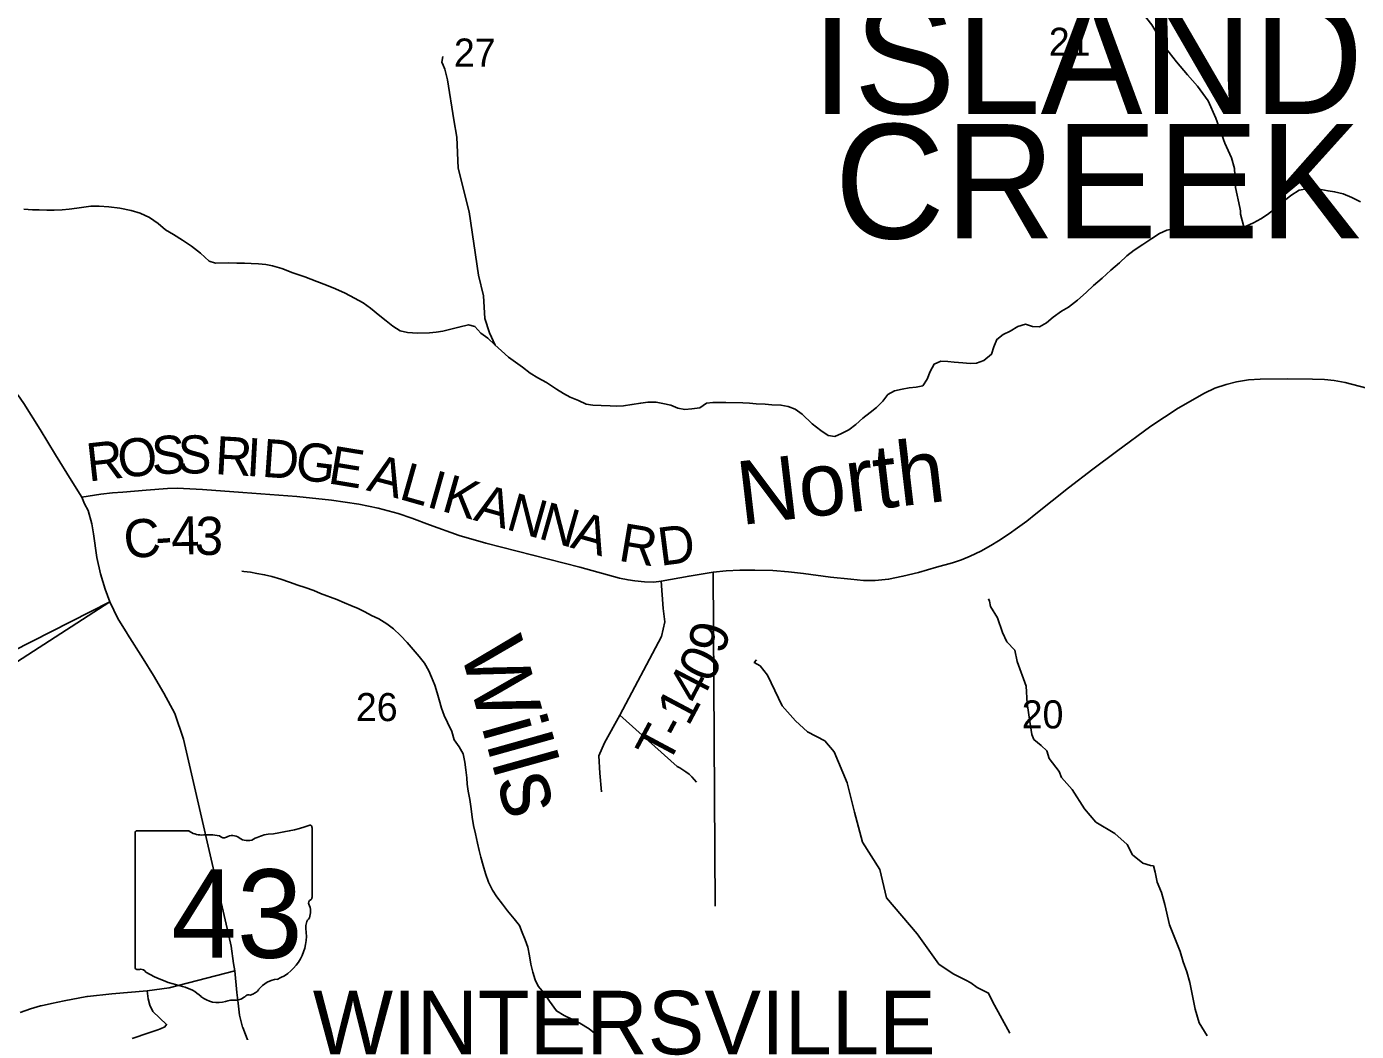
# Model space of a CAD drawing. Extents: x 0 to 34, y 0 to 22.
# Drawn here: x 5.55 to 7.533, y 16.768 to 18.266 of the extents above; entities that cross this region are included whole.
import ezdxf

# ---------------------------------------------------------------- set-up
doc = ezdxf.new("R2010")
doc.units = 0
for name, color, linetype in [('GM_X_Corporation_Text', 7, 'Continuous'), ('GM_X_County_Road', 7, 'Continuous'), ('GM_X_County_Road_Text', 7, 'Continuous'), ('GM_X_Minor_River', 7, 'Continuous'), ('GM_X_Minor_River_Text', 7, 'Continuous'), ('GM_X_Section_Text', 7, 'Continuous'), ('GM_X_State_Location', 7, 'Continuous'), ('GM_X_State_Route', 7, 'Continuous'), ('GM_X_State_Shield', 7, 'Continuous'), ('GM_X_Township_Road', 7, 'Continuous'), ('GM_X_Township_Road_Text', 7, 'Continuous'), ('GM_X_Township_Text', 7, 'Continuous'), ('SH_Data', 7, 'Continuous')]:
    doc.layers.add(name, color=color, linetype=linetype)

msp = doc.modelspace()

# ---------------------------------------------------------------- linework, layer by layer
at = {"layer": 'GM_X_County_Road'}
for points in [[(5.6321, 17.5648), (5.6607, 17.5691), (5.6781, 17.5712), (5.6934, 17.572), (5.7284, 17.5749), (5.7602, 17.5774), (5.7743, 17.5782), (5.8124, 17.5762), (5.8723, 17.5714), (5.9527, 17.5655), (6.0047, 17.5601), (6.0452, 17.554), (6.074, 17.5481), (6.1042, 17.5401), (6.1244, 17.5334), (6.1509, 17.5232), (6.1949, 17.5073), (6.2349, 17.4961), (6.305, 17.4782), (6.3752, 17.46), (6.4342, 17.444), (6.4468, 17.4412), (6.4571, 17.4398), (6.4713, 17.4384), (6.4851, 17.4379), (6.4965, 17.4392), (6.5378, 17.447), (6.5739, 17.453), (6.5934, 17.455), (6.6136, 17.4558), (6.636, 17.4559), (6.6628, 17.4553), (6.6863, 17.4534), (6.7087, 17.4508), (6.7487, 17.4455), (6.7791, 17.4421), (6.7978, 17.4405), (6.8152, 17.4402), (6.8353, 17.4423), (6.8568, 17.4468), (6.8802, 17.4525), (6.9071, 17.46), (6.9307, 17.4668), (6.9442, 17.4712), (6.9573, 17.4766), (6.973, 17.4843), (6.9879, 17.4927), (6.9992, 17.4997), (7.0151, 17.51), (7.0277, 17.5191), (7.0414, 17.529), (7.0548, 17.5399), (7.1036, 17.5784), (7.14, 17.6063), (7.1752, 17.6329), (7.2265, 17.6705), (7.2672, 17.6972), (7.3067, 17.7198), (7.3219, 17.727), (7.3387, 17.7328), (7.3544, 17.7367), (7.3722, 17.7393), (7.3898, 17.7406), (7.4303, 17.741), (7.4675, 17.7405), (7.4853, 17.7399), (7.5, 17.7385), (7.5164, 17.7354), (7.5485, 17.7269)], [(5.7439, 16.7699), (5.7495, 16.7717), (5.7561, 16.7747), (5.7586, 16.7785), (5.7382, 16.7979), (5.7337, 16.8072), (5.7311, 16.8168), (5.7296, 16.8288)], [(5.7074, 16.7573), (5.732, 16.7659), (5.7439, 16.7699)]]:
    msp.add_lwpolyline(points, dxfattribs=at)
at = {"layer": 'GM_X_Minor_River'}
for points in [[(7.3654, 17.9677), (7.3601, 17.9865), (7.3601, 17.9915), (7.3592, 17.9964), (7.353, 18.0263), (7.3514, 18.0545), (7.3469, 18.0707), (7.3367, 18.0926), (7.3232, 18.1296), (7.3122, 18.1553), (7.2959, 18.1771), (7.2812, 18.194), (7.2646, 18.2134), (7.2484, 18.2345), (7.2278, 18.2687), (7.2034, 18.2995), (7.1579, 18.3269), (7.1012, 18.348), (7.0317, 18.3655), (7.0137, 18.3807), (6.9548, 18.4193), (6.9266, 18.4318), (6.9232, 18.4344)], [(6.2486, 17.7914), (6.2402, 17.8094), (6.2333, 17.8309), (6.2312, 17.8647), (6.2239, 17.8954), (6.2097, 17.9902), (6.1935, 18.0549), (6.1915, 18.1013), (6.1873, 18.127), (6.1775, 18.1866), (6.1738, 18.2028), (6.1711, 18.2089), (6.1691, 18.213), (6.1705, 18.2218)], [(7.539, 18.0051), (7.5262, 18.0116), (7.5131, 18.0169), (7.5005, 18.0199), (7.4909, 18.0211), (7.4802, 18.0231), (7.4695, 18.0246), (7.4589, 18.0243), (7.4476, 18.0221), (7.4353, 18.0141), (7.4249, 18.0061), (7.4119, 17.9951), (7.4004, 17.986), (7.3907, 17.9796), (7.3795, 17.9735), (7.3686, 17.9686), (7.3566, 17.9652), (7.3464, 17.963), (7.3327, 17.9626), (7.3182, 17.9629), (7.3038, 17.9643), (7.2912, 17.9654), (7.2813, 17.9659), (7.2718, 17.9656), (7.2619, 17.9649), (7.2506, 17.9626), (7.2393, 17.9577), (7.2278, 17.9501), (7.2147, 17.9414)], [(6.1178, 17.8099), (6.1071, 17.8126), (6.0962, 17.8195), (6.0864, 17.8275), (6.0767, 17.8348), (6.0627, 17.8462), (6.0518, 17.8542), (6.039, 17.8614), (6.0251, 17.8686), (6.0108, 17.8754), (5.997, 17.8806), (5.9827, 17.8863), (5.965, 17.8929), (5.9469, 17.8992), (5.9308, 17.9055), (5.9166, 17.9097), (5.9066, 17.9116), (5.8956, 17.9124), (5.8849, 17.9128), (5.875, 17.9137), (5.8636, 17.9137), (5.8514, 17.9141), (5.8317, 17.9134), (5.8221, 17.9166), (5.8092, 17.9283), (5.7959, 17.9389), (5.7823, 17.9476), (5.7691, 17.956), (5.7571, 17.9632), (5.7462, 17.9724), (5.733, 17.9814), (5.7191, 17.9879), (5.7057, 17.992), (5.6892, 17.9953), (5.6728, 17.9974), (5.6579, 17.9985), (5.6458, 17.9985), (5.6246, 17.9955), (5.6136, 17.994), (5.603, 17.9929), (5.5908, 17.9926), (5.5802, 17.9926), (5.5688, 17.993), (5.5589, 17.9931), (5.5459, 17.9938)], [(7.2147, 17.9414), (7.2017, 17.933), (7.1906, 17.9243), (7.1799, 17.914), (7.1669, 17.903), (7.154, 17.8912), (7.141, 17.8801), (7.1303, 17.8699), (7.1173, 17.8584), (7.1036, 17.8481), (7.0935, 17.8417), (7.0809, 17.833), (7.0709, 17.8247), (7.0604, 17.8186), (7.0501, 17.8191), (7.0394, 17.8225), (7.0281, 17.8191), (7.0169, 17.8123), (7.0064, 17.807), (6.9968, 17.7999), (6.9922, 17.7887), (6.9887, 17.7776), (6.9776, 17.7681), (6.9667, 17.7644), (6.9572, 17.7641), (6.9461, 17.7648), (6.9332, 17.766), (6.9236, 17.7668), (6.9134, 17.7672), (6.9032, 17.7627), (6.8975, 17.7519), (6.8929, 17.7407), (6.8864, 17.7306), (6.8766, 17.7288), (6.8663, 17.7277), (6.8557, 17.7255), (6.844, 17.7229), (6.8343, 17.7176), (6.827, 17.7079), (6.8174, 17.6984), (6.8078, 17.6909), (6.797, 17.6826), (6.7867, 17.6731), (6.7763, 17.6652), (6.7654, 17.6595), (6.7553, 17.655), (6.7454, 17.6566), (6.7345, 17.6639), (6.7216, 17.6741), (6.7067, 17.6885), (6.6959, 17.6958), (6.6855, 17.6996), (6.6748, 17.7019), (6.6611, 17.7023), (6.6515, 17.7031), (6.6378, 17.7038), (6.6279, 17.7046), (6.618, 17.7051), (6.5929, 17.7058), (6.583, 17.7055), (6.5735, 17.7056), (6.564, 17.7049), (6.554, 17.6978), (6.5419, 17.6962), (6.5316, 17.6955), (6.5213, 17.6975), (6.5109, 17.7017), (6.4986, 17.7044), (6.4887, 17.706), (6.4765, 17.706), (6.4659, 17.7049), (6.4527, 17.7026), (6.4402, 17.7006), (6.4303, 17.7003), (6.4201, 17.7008), (6.4067, 17.7015), (6.3945, 17.7019), (6.3842, 17.7034), (6.373, 17.7088), (6.3607, 17.7137), (6.3507, 17.7191), (6.3402, 17.7256), (6.3251, 17.7354), (6.3123, 17.7426), (6.301, 17.7495), (6.2897, 17.7583), (6.2789, 17.7659), (6.2684, 17.7732), (6.2582, 17.7827), (6.248, 17.7919), (6.2378, 17.8015), (6.2273, 17.8092), (6.2186, 17.8188), (6.2087, 17.8215), (6.1947, 17.818), (6.1804, 17.8145), (6.1706, 17.8123), (6.1607, 17.8105), (6.1509, 17.8094), (6.133, 17.8089), (6.1178, 17.8099)], [(6.1688, 17.2499), (6.1654, 17.2623), (6.1624, 17.2729), (6.1586, 17.2845), (6.1537, 17.2962), (6.1496, 17.3059), (6.1435, 17.3172), (6.1356, 17.3272), (6.1265, 17.3375), (6.1175, 17.3479), (6.1076, 17.3582), (6.0971, 17.3682), (6.0869, 17.3758), (6.0753, 17.3831), (6.0645, 17.3884), (6.0541, 17.3938), (6.0444, 17.3988), (6.0336, 17.403), (6.024, 17.4069), (6.0128, 17.4119), (5.9882, 17.421), (5.9782, 17.4253), (5.9655, 17.4298), (5.9543, 17.4332), (5.942, 17.4378), (5.929, 17.4423), (5.9155, 17.4461), (5.9048, 17.4488), (5.8933, 17.4507), (5.8838, 17.4527), (5.8739, 17.4539), (5.8708, 17.4542)], [(7.3105, 16.7615), (7.2988, 16.7807), (7.2924, 16.8015), (7.2849, 16.8409), (7.28, 16.8571), (7.2745, 16.8719), (7.2701, 16.887), (7.2641, 16.9021), (7.2542, 16.927), (7.2473, 16.9573), (7.2424, 16.9751), (7.2357, 16.9906), (7.2332, 17.0057), (7.2304, 17.0148), (7.2262, 17.0155), (7.2144, 17.0191), (7.1991, 17.0314), (7.1912, 17.0468), (7.1728, 17.0633), (7.1445, 17.0803), (7.1275, 17.0998), (7.1093, 17.1287), (7.0931, 17.1467), (7.0899, 17.1558), (7.0748, 17.1749), (7.0716, 17.1866), (7.0631, 17.1945), (7.052, 17.2034), (7.0488, 17.2109), (7.0462, 17.2303), (7.0423, 17.2568), (7.0404, 17.283), (7.0272, 17.3197), (7.0235, 17.3367), (7.0116, 17.349), (7.0053, 17.363), (6.9977, 17.3849), (6.9876, 17.4015), (6.9859, 17.4094), (6.9844, 17.4128)], [(7.0163, 16.7654), (6.9905, 16.8128), (6.9846, 16.8253), (6.9675, 16.8337), (6.9579, 16.8404), (6.9506, 16.8445), (6.9445, 16.8474), (6.9319, 16.854), (6.9101, 16.8685), (6.878, 16.9136), (6.8324, 16.9672), (6.8222, 17.0095), (6.7965, 17.0502), (6.7848, 17.0952), (6.7734, 17.1387), (6.7544, 17.1848), (6.7401, 17.2012), (6.7146, 17.2149), (6.6965, 17.2313), (6.6768, 17.2534), (6.6549, 17.299), (6.644, 17.3129), (6.6352, 17.3181), (6.6382, 17.3219)], [(6.3993, 16.7636), (6.3891, 16.7721), (6.3748, 16.7803), (6.3628, 16.7864), (6.3516, 16.7918), (6.34, 16.7986), (6.3297, 16.8131), (6.3225, 16.8247), (6.313, 16.8354), (6.3085, 16.8452), (6.3047, 16.8565), (6.3021, 16.8682), (6.2998, 16.8806), (6.2975, 16.8935), (6.2933, 16.9048), (6.2892, 16.9157), (6.2851, 16.9262), (6.2768, 16.9358), (6.2673, 16.9477), (6.2594, 16.9577), (6.2514, 16.9688), (6.2446, 16.9789), (6.2386, 16.9905), (6.2344, 17.0033), (6.2306, 17.0153), (6.2275, 17.0278), (6.2249, 17.038), (6.2223, 17.0489), (6.2192, 17.0625), (6.2165, 17.075), (6.2146, 17.0875), (6.2131, 17.1), (6.2107, 17.1139), (6.2084, 17.1264), (6.207, 17.1366), (6.2063, 17.1461), (6.2052, 17.1579), (6.2037, 17.1696), (6.201, 17.1817), (6.195, 17.1925), (6.1874, 17.2026), (6.184, 17.215), (6.1775, 17.2285), (6.1726, 17.239), (6.1688, 17.2499)]]:
    msp.add_lwpolyline(points, dxfattribs=at)
at = {"layer": 'GM_X_State_Route'}
for points in [[(5.674, 17.4084), (5.6669, 17.4275), (5.6602, 17.4502), (5.6549, 17.4748), (5.6496, 17.5101), (5.6474, 17.5249), (5.6416, 17.5448), (5.6365, 17.5549), (5.6321, 17.5648), (5.6162, 17.5898), (5.5931, 17.6278), (5.5703, 17.6654), (5.5456, 17.704), (5.537, 17.7172)], [(5.6999, 17.3613), (5.6858, 17.3838), (5.674, 17.4084)], [(5.8605, 16.8585), (5.8585, 16.8695), (5.855, 16.8952), (5.849, 16.9213), (5.7839, 17.2037), (5.7709, 17.2423), (5.7544, 17.2724), (5.7393, 17.2989), (5.7237, 17.3235), (5.7004, 17.3605), (5.6999, 17.3613)], [(5.6399, 16.8199), (5.6409, 16.82), (5.6772, 16.8239), (5.7296, 16.8288), (5.7627, 16.8332), (5.8605, 16.8585)], [(5.8722, 16.7737), (5.8719, 16.7746), (5.8675, 16.7924), (5.8656, 16.8103), (5.8636, 16.8261), (5.8605, 16.8585)], [(5.5718, 16.8064), (5.5871, 16.8098), (5.6059, 16.8136), (5.6399, 16.8199)], [(5.5403, 16.7965), (5.5559, 16.802), (5.5709, 16.8062), (5.5718, 16.8064)], [(5.9876, 16.6096), (5.9495, 16.6643), (5.9232, 16.6955), (5.9035, 16.7144), (5.8915, 16.7293), (5.8827, 16.7466), (5.8722, 16.7737)]]:
    msp.add_lwpolyline(points, dxfattribs=at)
at = {"layer": 'GM_X_State_Shield'}
for p, q in [((5.7119, 17.0639), (5.7119, 16.8637)), ((5.7917, 17.0673), (5.7145, 17.0673)), ((5.9756, 16.9676), (5.9756, 17.0723)), ((5.9755, 16.9676), (5.9756, 16.9676))]:
    msp.add_line(p, q, dxfattribs=at)
for centre, radius, start, end in [((5.8816, 17.3401), 0.2796, 275.8445, 288.9065), ((5.9726, 17.0727), 0.00294, 351.8621, 97.738), ((5.7149, 17.0643), 0.00305, 98.1301, 188.1301), ((5.8101, 17.0905), 0.0296, 231.6195, 271.1119), ((5.8199, 16.9549), 0.1064, 80.4867, 94.9883), ((5.8441, 17.0653), 0.00855, 219.7921, 297.1024), ((5.8566, 17.0422), 0.0178, 54.4667, 119.1411), ((5.8795, 17.0739), 0.0214, 233.8562, 294.8282), ((5.9173, 17.0062), 0.0563, 97.3462, 120.7689), ((5.9749, 16.9599), 0.00454, 107.944, 210.337), ((5.946, 16.9467), 0.0273, 340.033, 23.6496), ((5.9724, 16.9672), 0.00314, 289.6038, 7.7341), ((5.9861, 16.9238), 0.0198, 136.8065, 186.9296), ((5.8973, 16.9104), 0.0699, 292.3089, 8.9858), ((5.7149, 16.8633), 0.00308, 171.9584, 258.3066), ((5.7154, 16.8838), 0.0235, 267.339, 280.6039), ((5.7202, 16.8522), 0.00848, 29.7484, 93.2717), ((5.8273, 17.032), 0.2019, 240.4129, 257.1985), ((5.9268, 16.8076), 0.0383, 94.4031, 142.5768), ((5.7671, 16.7738), 0.0632, 47.1842, 75.836), ((5.8354, 16.8512), 0.0401, 230.7004, 286.2918), ((5.8615, 16.8362), 0.0214, 268.777, 315.5493), ((5.8808, 16.8168), 0.00601, 65.7517, 132.6484), ((5.8783, 16.8443), 0.0226, 282.8732, 323.2771), ((5.8586, 16.782), 0.0329, 85.6951, 111.2099)]:
    msp.add_arc(centre, radius, start, end, dxfattribs=at)
at = {"layer": 'GM_X_Township_Road'}
msp.add_line((6.5767, 16.955), (6.5739, 17.453), dxfattribs=at)
for points in [[(6.4073, 17.1252), (6.4049, 17.1533), (6.4034, 17.179), (6.4119, 17.1985), (6.4346, 17.2398), (6.4969, 17.3567), (6.5016, 17.3785), (6.4992, 17.3988), (6.4965, 17.4392)], [(6.4346, 17.2398), (6.5203, 17.1631), (6.5242, 17.161), (6.5288, 17.1582), (6.5332, 17.1551), (6.5378, 17.1515), (6.5421, 17.1475), (6.5456, 17.1438), (6.5491, 17.1397)]]:
    msp.add_lwpolyline(points, dxfattribs=at)
at = {"layer": 'SH_Data'}
msp.add_lwpolyline([(5.1027, 17.0396), (5.674, 17.4084), (4.9484, 17.0396)], close=True, dxfattribs=at)

# ---------------------------------------------------------------- texts
at = {"layer": 'GM_X_Corporation_Text'}
msp.add_text('WINTERSVILLE', height=0.094697, rotation=0, dxfattribs=at).set_placement((5.9768, 16.7339))
at = {"layer": 'GM_X_County_Road_Text'}
for s, rotation, p in [('O', 6.0731, (5.6886, 17.5929)), ('S', 3.1804, (5.7376, 17.5981)), ('S', 359.4346, (5.7749, 17.6002)), ('R', 356.794, (5.83, 17.599)), ('I', 356.7903, (5.8766, 17.5964)), ('D', 355.9567, (5.8997, 17.5951)), ('R', 6.257, (5.6423, 17.5878)), ('G', 352.7937, (5.9487, 17.5917)), ('E', 350.6765, (5.9978, 17.5855)), ('A', 345.2446, (6.0554, 17.5751)), ('L', 344.1788, (6.1035, 17.5624)), ('I', 344.1775, (6.1444, 17.5508)), ('K', 344.1762, (6.1668, 17.5445)), ('A', 344.1773, (6.2149, 17.5308)), ('N', 344.1797, (6.263, 17.5172)), ('N', 344.1762, (6.3112, 17.5036)), ('C', 5.7549, (5.6975, 17.4724)), ('4', 1.2074, (5.7661, 17.4786)), ('3', 357.8762, (5.8002, 17.4793)), ('A', 344.1846, (6.3593, 17.4899)), ('R', 350.5919, (6.431, 17.4701)), ('D', 7.2488, (6.495, 17.4621)), ('-', 3.8826, (5.7435, 17.4771))]:
    msp.add_text(s, height=0.0568, rotation=rotation, dxfattribs=at).set_placement(p)
at = {"layer": 'GM_X_Minor_River_Text'}
for s, height, rotation, p in [('North', 0.09471, 6.7071, (6.6153, 17.5229)), ('Wills', 0.09467, 285.6526, (6.1956, 17.3385))]:
    msp.add_text(s, height=height, rotation=rotation, dxfattribs=at).set_placement(p)
at = {"layer": 'GM_X_Section_Text'}
for s, p in [('21', (7.0743, 18.2226)), ('27', (6.1872, 18.2065)), ('26', (6.041, 17.2307)), ('20', (7.0339, 17.2198))]:
    msp.add_text(s, height=0.04186, rotation=0, dxfattribs=at).set_placement(p)
at = {"layer": 'GM_X_State_Location'}
msp.add_text('43', height=0.000189, rotation=0, dxfattribs=at).set_placement((5.7931, 16.9367))
for s, p in [('s', (5.8408, 16.9505)), ('r', (5.8407, 16.9505))]:
    msp.add_text(s, height=0.000189, dxfattribs=at).set_placement(p)
at = {"layer": 'GM_X_State_Shield'}
msp.add_text('43', height=0.13184, dxfattribs=at).set_placement((5.7655, 16.8778))
at = {"layer": 'GM_X_Township_Road_Text'}
for s, rotation, p in [('9', 75.8528, (6.5901, 17.3289)), ('0', 64.0846, (6.5705, 17.2855)), ('4', 62.612, (6.5536, 17.253)), ('1', 62.0795, (6.537, 17.2216)), ('T', 61.892, (6.5059, 17.1633)), ('-', 61.9157, (6.5259, 17.2008))]:
    msp.add_text(s, height=0.0568, rotation=rotation, dxfattribs=at).set_placement(p)
at = {"layer": 'GM_X_Township_Text'}
for s, p in [('ISLAND', (6.7201, 18.1359)), ('CREEK', (6.7547, 17.9503))]:
    msp.add_text(s, height=0.17045, rotation=0, dxfattribs=at).set_placement(p)

doc.saveas('drawing.dxf')
